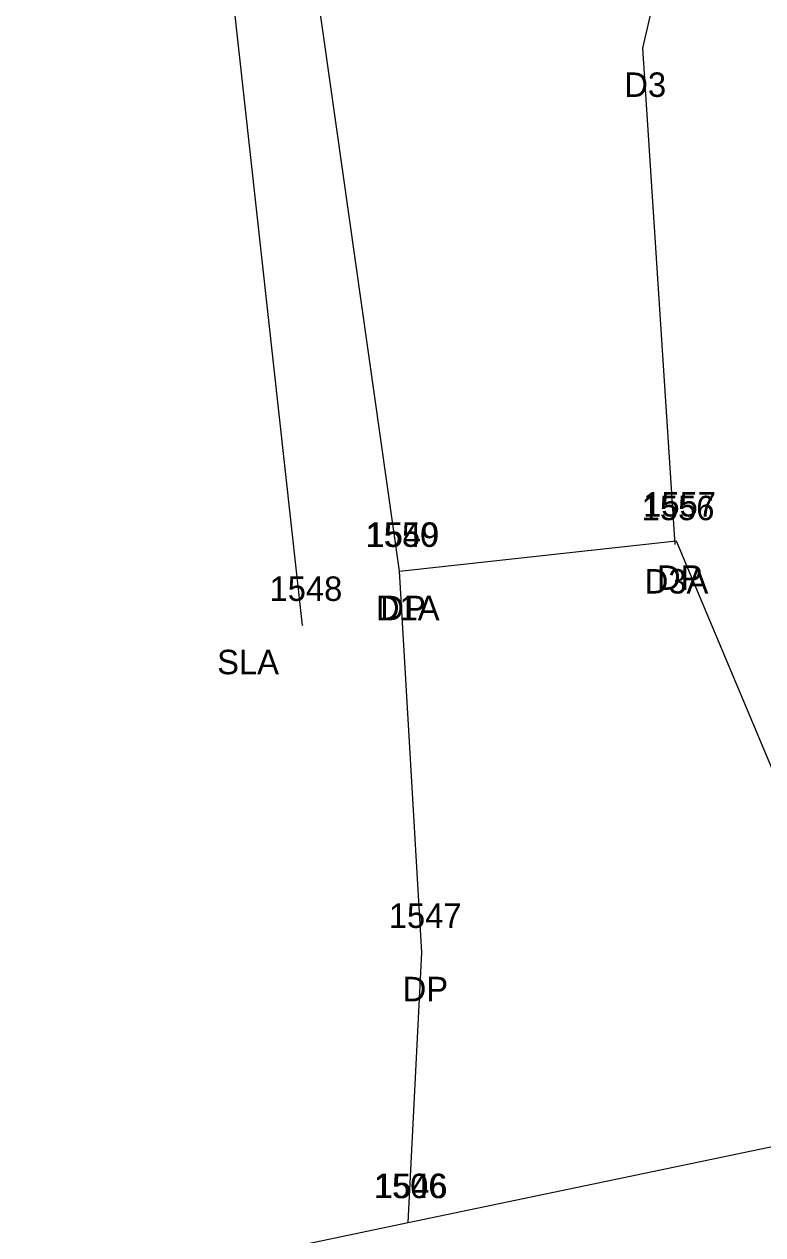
# Model space of a CAD drawing. Extents: x 1965304 to 1970247, y 1117014 to 1118201.
# Drawn here: x 1966562.69 to 1966592.88, y 1117408.09 to 1117457.62 of the extents above; entities that cross this region are included whole.
import ezdxf

# ---------------------------------------------------------------- set-up
doc = ezdxf.new("R2010")
doc.units = 0
for name, color, linetype in [('RD_EX_Driveway', 7, 'Continuous'), ('RD_EX_Driveway_txCode', 7, 'Continuous'), ('RD_EX_Road', 7, 'Continuous'), ('RD_EX_Road_txCode', 7, 'Continuous'), ('RD_EX_VEG', 7, 'Continuous'), ('RD_EX_VEG_txCode', 7, 'Continuous'), ('RD_SMD_Locator', 7, 'Continuous')]:
    doc.layers.add(name, color=color, linetype=linetype)

msp = doc.modelspace()

# ---------------------------------------------------------------- linework, layer by layer
at = {"layer": 'RD_EX_Driveway'}
for points in [[(1966578.028, 1117435.239), (1966571.581, 1117480.753), (1966567.97, 1117515.311), (1966576.556, 1117516.6), (1966582.112, 1117483.547), (1966603.624, 1117509.102), (1966634.749, 1117528.345), (1966662.085, 1117526.43), (1966689.524, 1117514.663), (1966711.523, 1117497.722), (1966730.008, 1117478.512), (1966744.031, 1117462.693), (1966734.107, 1117458.19)], [(1966589.3, 1117436.331), (1966587.977, 1117456.65), (1966594.083, 1117483.042), (1966609.697, 1117504.074), (1966638.325, 1117518.314), (1966661.317, 1117517.134), (1966685.434, 1117507.038), (1966705.558, 1117491.043), (1966722.871, 1117472.119), (1966734.107, 1117458.19)], [(1966578.388, 1117408.593), (1966578.939, 1117419.648), (1966578.028, 1117435.239), (1966589.341, 1117436.481), (1966594.391, 1117424.44), (1966597.459, 1117418.815), (1966604.527, 1117414.058)]]:
    msp.add_lwpolyline(points, dxfattribs=at)
at = {"layer": 'RD_EX_Road'}
msp.add_lwpolyline([(1966031.823, 1117232.956), (1966074.66, 1117252.15), (1966117.782, 1117271.581), (1966161.06, 1117290.483), (1966205.406, 1117309.226), (1966251.249, 1117327.393), (1966297.245, 1117343.102), (1966344.085, 1117357.038), (1966390.785, 1117368.561), (1966438.122, 1117379.082), (1966484.547, 1117389.131), (1966531.199, 1117398.733), (1966578.388, 1117408.593), (1966604.527, 1117414.058), (1966624.537, 1117418.323), (1966671.319, 1117428.348), (1966716.506, 1117439.32), (1966736.604, 1117445.59), (1966754.133, 1117451.442), (1966759.658, 1117453.517), (1966769.512, 1117457.475)], dxfattribs=at)
at = {"layer": 'RD_EX_VEG'}
msp.add_line((1966574.062, 1117433.028), (1966570.646, 1117464.069), dxfattribs=at)
at = {"layer": 'RD_SMD_Locator'}
for centre in [(1966587.977, 1117456.65), (1966587.977, 1117456.65), (1966589.341, 1117436.481), (1966589.341, 1117436.481), (1966589.3, 1117436.331), (1966589.3, 1117436.331), (1966578.028, 1117435.239), (1966578.028, 1117435.239), (1966578.028, 1117435.239), (1966578.028, 1117435.239), (1966574.062, 1117433.028), (1966574.062, 1117433.028), (1966578.939, 1117419.648), (1966578.939, 1117419.648), (1966578.388, 1117408.593), (1966578.388, 1117408.593), (1966578.388, 1117408.593), (1966578.388, 1117408.593)]:
    msp.add_circle(centre, 0.001, dxfattribs=at)

# ---------------------------------------------------------------- texts
at = {"layer": 'RD_EX_Driveway_txCode'}
for s, p in [('D3', (1966587.221, 1117454.65)), ('D3', (1966587.221, 1117454.65)), ('1557', (1966587.995, 1117437.481)), ('1557', (1966587.995, 1117437.481)), ('1556', (1966587.93, 1117437.331)), ('1556', (1966587.93, 1117437.331)), ('1550', (1966576.642, 1117436.239)), ('1550', (1966576.642, 1117436.239)), ('1549', (1966576.681, 1117436.239)), ('1549', (1966576.681, 1117436.239)), ('DP', (1966588.561, 1117434.481)), ('DP', (1966588.561, 1117434.481)), ('D3A', (1966588.056, 1117434.331)), ('D3A', (1966588.056, 1117434.331)), ('D1A', (1966577.067, 1117433.239)), ('D1A', (1966577.067, 1117433.239)), ('DP', (1966577.248, 1117433.239)), ('DP', (1966577.248, 1117433.239)), ('1547', (1966577.592, 1117420.648)), ('1547', (1966577.592, 1117420.648)), ('DP', (1966578.159, 1117417.648)), ('DP', (1966578.159, 1117417.648)), ('1546', (1966577.018, 1117409.593)), ('1546', (1966577.018, 1117409.593))]:
    msp.add_text(s, height=1, dxfattribs=at).set_placement(p)
at = {"layer": 'RD_EX_Road_txCode'}
msp.add_text('1506', height=1, dxfattribs=at).set_placement((1966576.978, 1117409.593))
msp.add_text('1506', height=1, dxfattribs=at).set_placement((1966576.978, 1117409.593))
at = {"layer": 'RD_EX_VEG_txCode'}
for s, p in [('1548', (1966572.716, 1117434.028)), ('1548', (1966572.716, 1117434.028)), ('SLA', (1966570.574, 1117431.028)), ('SLA', (1966570.574, 1117431.028))]:
    msp.add_text(s, height=1, dxfattribs=at).set_placement(p)

doc.saveas('drawing.dxf')
